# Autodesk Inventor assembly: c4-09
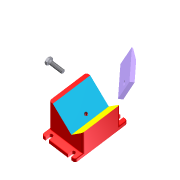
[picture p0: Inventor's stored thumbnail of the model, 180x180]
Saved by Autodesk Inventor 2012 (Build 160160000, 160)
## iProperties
Created: 2010-11
Part Number: c4-09
Document SubType Name: Assembly
Designer: Beta-8540w
Author: Beta-8540w
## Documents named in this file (4)
- C:\Users\VMuser\Desktop\Inventor 2012 Essentials\Assemblies\Chapter 4\c4-09.iam
- C:\Users\VMuser\Desktop\Inventor 2012 Essentials\Content Center Files\en-US\ISO 4017\ISO 4017 - M10 x 35ISO.ipt
- C:\Users\VMuser\Desktop\Inventor 2012 Essentials\Parts\Chapter 4\c4-09.ipt
- C:\Users\VMuser\Desktop\Inventor 2012 Essentials\Parts\Chapter 4\c4-10.ipt
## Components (3 placed, 3 different names)
1. c4-09:1
2. c4-10:1
3. ISO 4017 M10 x 35:1
